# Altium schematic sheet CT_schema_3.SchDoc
size 276 x 169 mm
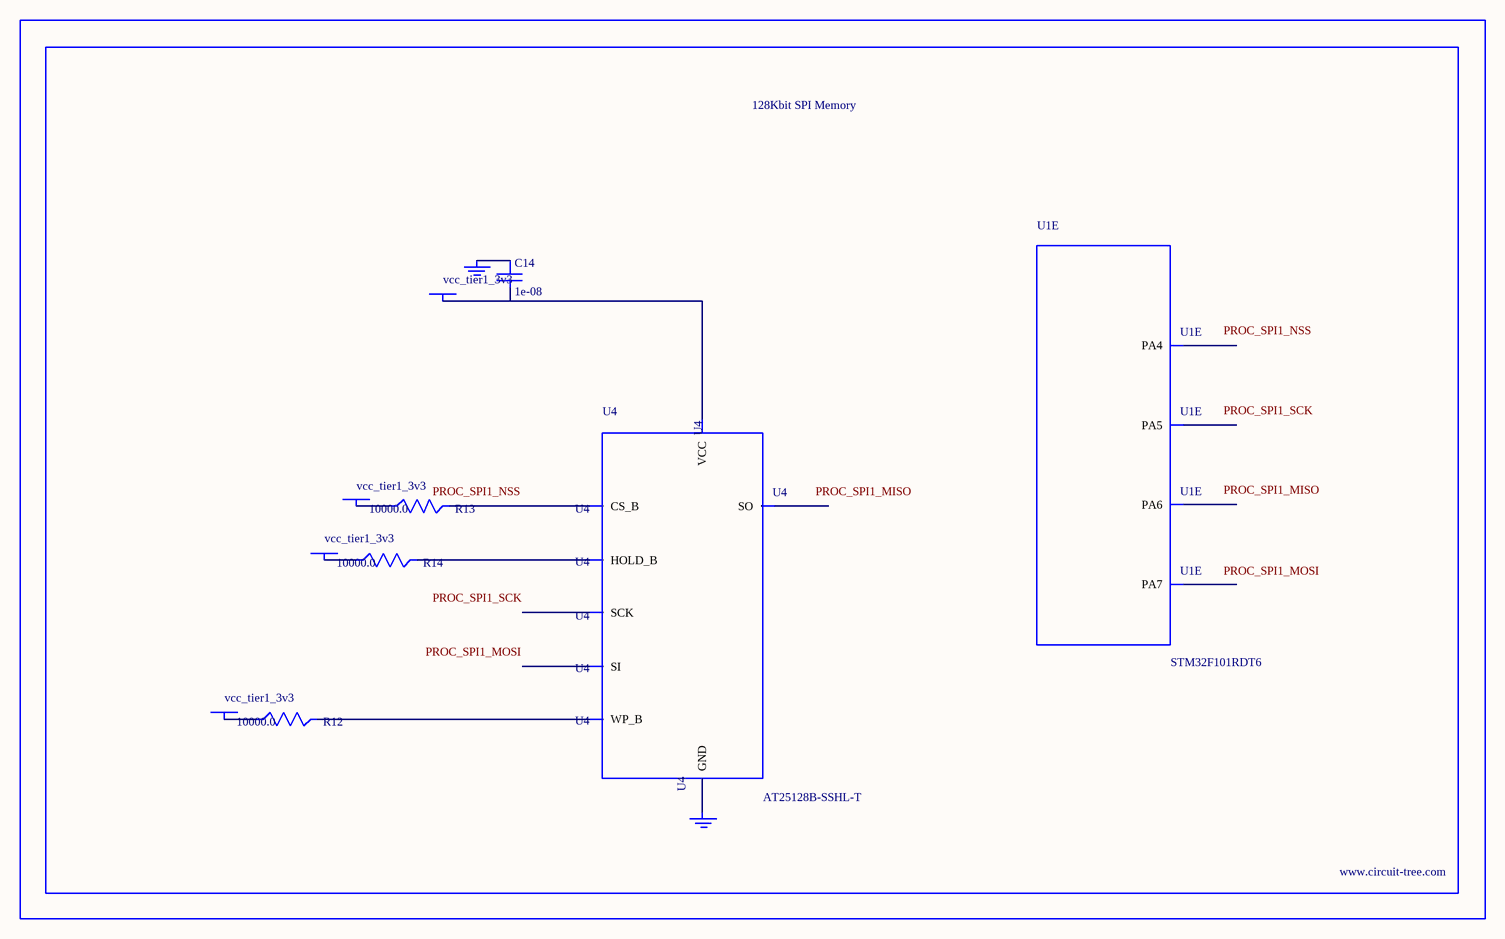
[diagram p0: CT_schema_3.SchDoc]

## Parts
BORDER2  (no value)
C14  1e-08  [C0402]
GND_INSTANCE_2_0  (no value)
GND_INSTANCE_2_1  (no value)
POWER_INSTANCE_2_0  vcc_tier1_3v3
POWER_INSTANCE_2_1  vcc_tier1_3v3
POWER_INSTANCE_2_2  vcc_tier1_3v3
POWER_INSTANCE_2_3  vcc_tier1_3v3
R12  10000.0  [R0603]
R13  10000.0  [R0603]
R14  10000.0  [R0603]
U1  STM32F101RDT6  [LQFP64]  (part E of 7)
U4  AT25128B-SSHL-T  [SOIC-8]

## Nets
NetC14_1: C14.1 GND_INSTANCE_2_0.0(GND)
NetC14_2: C14.2 POWER_INSTANCE_2_3.0(PWR) U4.8(VCC)
NetGND_INSTANCE_2_1_0: GND_INSTANCE_2_1.0(GND) U4.4(GND)
NetPOWER_INSTANCE_2_0_0: POWER_INSTANCE_2_0.0(PWR) R13.1
NetPOWER_INSTANCE_2_1_0: POWER_INSTANCE_2_1.0(PWR) R12.1
NetPOWER_INSTANCE_2_2_0: POWER_INSTANCE_2_2.0(PWR) R14.1
NetR12_2: R12.2 U4.3(WP_B)
NetR13_2: R13.2 U4.1(CS_B)
NetR14_2: R14.2 U4.7(HOLD_B)

Not connected (* = marked no-connect by the designer): U1 20(PA4) 21(PA5) 22(PA6) 23(PA7); U4 2(SO) 5(SI) 6(SCK)

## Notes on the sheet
- Labels drawn without touching a wire or pin: PROC_SPI1_MISO, PROC_SPI1_MOSI, PROC_SPI1_NSS, PROC_SPI1_SCK

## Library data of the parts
BORDER2 = BORDER_PAGE2
C14 = C0402C103K3RAC
GND_INSTANCE_2_0 GND_INSTANCE_2_1 = GND
POWER_INSTANCE_2_0-POWER_INSTANCE_2_3 = PWR
R12-R14 = RC0603JR-0710KL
